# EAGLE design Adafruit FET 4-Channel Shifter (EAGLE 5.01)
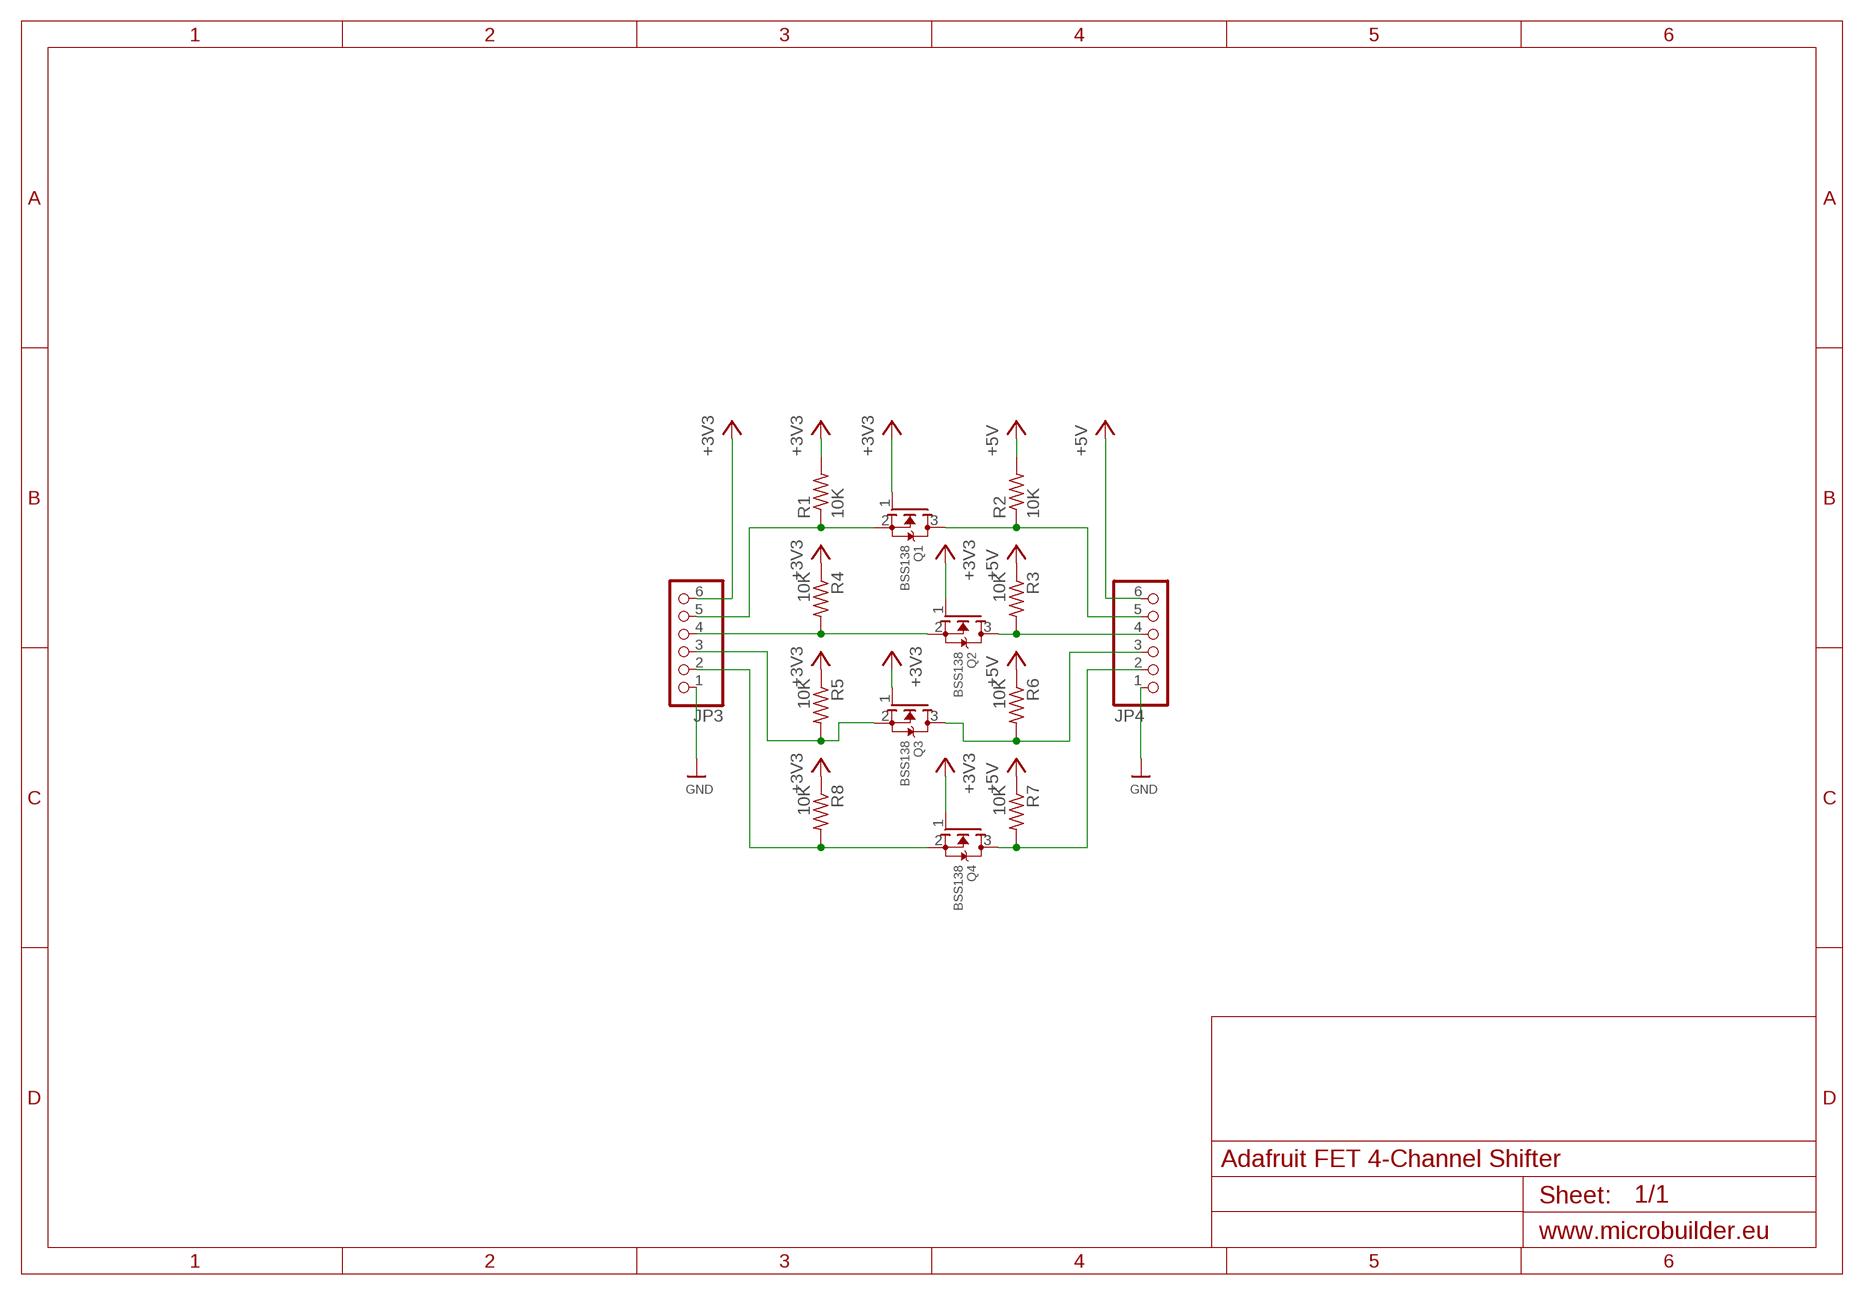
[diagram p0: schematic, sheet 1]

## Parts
JP3  PINHD-1X6CB  [1X06-CLEANBIG]
JP4  PINHD-1X6CB  [1X06-CLEANBIG]
Q1  BSS138  MOSFET-NREFLOW  [SOT23]
Q2  BSS138  MOSFET-NREFLOW  [SOT23]
Q3  BSS138  MOSFET-NREFLOW  [SOT23]
Q4  BSS138  MOSFET-NREFLOW  [SOT23]
R1  10K  R-US_R0805  [R0805]
R2  10K  R-US_R0805  [R0805]
R3  10K  R-US_R0805  [R0805]
R4  10K  R-US_R0805  [R0805]
R5  10K  R-US_R0805  [R0805]
R6  10K  R-US_R0805  [R0805]
R7  10K  R-US_R0805  [R0805]
R8  10K  R-US_R0805  [R0805]

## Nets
+3V3: JP3.6 Q1.1(G) Q2.1(G) Q3.1(G) Q4.1(G) R1.2 R4.1 R5.1 R8.1
+5V: JP4.6 R2.2 R3.1 R6.1 R7.1
GND: JP3.1 JP4.1
N$1: JP4.3 Q3.3(D) R6.2
N$2: JP4.5 Q1.3(D) R2.1
N$3: JP3.3 Q3.2(S) R5.2
N$4: JP3.2 Q4.2(S) R8.2
N$5: JP4.2 Q4.3(D) R7.2
N$6: JP3.4 Q2.2(S) R4.2
N$8: JP4.4 Q2.3(D) R3.2
N$9: JP3.5 Q1.2(S) R1.1

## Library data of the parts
JP3 JP4 = adafruit:PINHD-1X6: PIN HEADER
Q1-Q4 = adafruit:MOSFET-N: N-Channel Mosfet 2N7002E - 60V 260mA SOT23 [Digikey: 2N7002ET1GOSTR-ND] - REEL BSH103 - 30V 850mA SOT23 [Digikey: 568-5013-1-ND]
R1-R8 = adafruit:R-US_: RESISTOR, American symbol

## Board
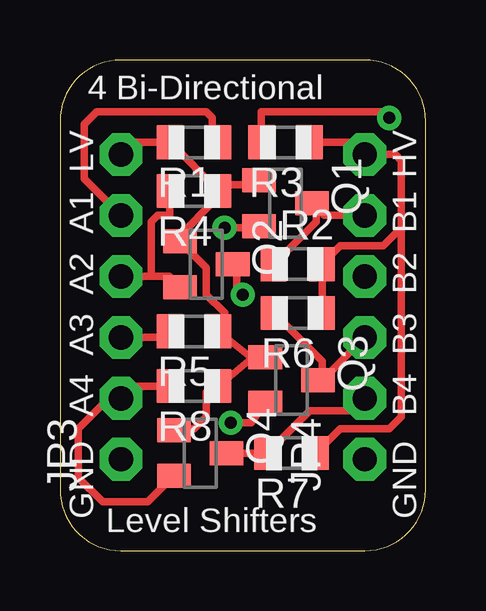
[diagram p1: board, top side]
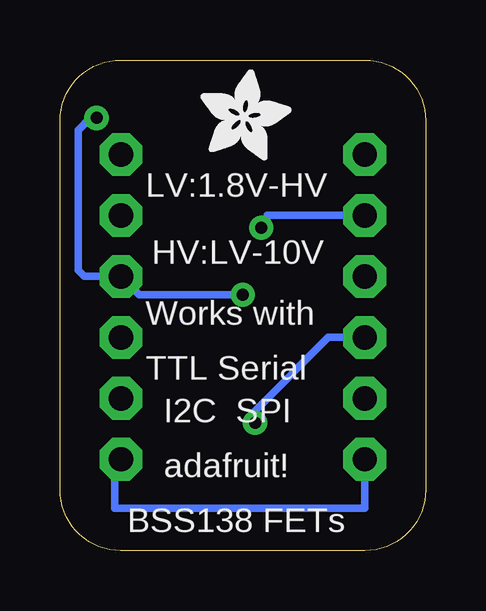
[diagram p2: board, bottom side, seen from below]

Size 15.24 x 20.45 mm. Coordinates in mm from the lower left corner, seen from the top.
Outline: 12.7,0 arc90 15.24,2.54 15.24,17.91 arc90 12.7,20.45 2.54,20.45 arc90 0,17.91 0,2.54 arc90 2.54,0 12.7,0
Copper layers (1*16): Top 0.035mm / dielectric 1.5mm / Bottom 0.035mm
Design rules "default *": minimum track width 8mil, minimum drill 0.4mm, track to track 8mil, track to pad 8mil, pad to pad 8mil, via to via 8mil, smd to smd 8mil, copper to edge 20mil, drill to drill 8mil, minimum pad ring 8mil, minimum via ring 10mil, stop-mask expansion 3mil, vias tented up to drill 20mil, thermal gap 8mil

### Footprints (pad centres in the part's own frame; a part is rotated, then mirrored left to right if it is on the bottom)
1X06-CLEANBIG = drill 1.016 pad 1.778 octagon: 1 -6.35,0; 2 -3.81,0; 3 -1.27,0; 4 1.27,0; 5 3.81,0; 6 6.35,0
SOT23 = smd 1 x 1.4: 1 -0.95,-1.1; 2 0.95,-1.1; 3 0,1.1
R0805 = smd 1.1 x 1.4: 1 -1,0; 2 1,0

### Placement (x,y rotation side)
JP3  2.54,10.16 90 top
JP4  12.7,10.16 90 top
Q1  9.4,14.48 270 top
Q2  6.1,11.94 270 top
Q3  9.65,7.11 270 top
Q4  5.84,4.06 270 top
R1  5.59,17.02 180 top
R2  9.91,11.94 0 top
R3  9.4,17.02 180 top
R4  5.59,14.99 180 top
R5  5.59,9.14 180 top
R6  9.91,9.91 180 top
R7  9.65,4.06 180 top
R8  5.59,6.86 180 top
U$1  [ADAFRUIT_3.5MM]  9.4,16.26 0 bottom

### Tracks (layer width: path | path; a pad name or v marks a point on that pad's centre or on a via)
+3V3
  Top 0.305: JP3.6 3.05,17.02 R1.2 6.62,14.99 | R4.1 6.62,14.99 | 6.62,14.99 6.86,14.99 | Q1.1 8.13,15.26 8.13,15.24 6.84,15.24 R4.1 | R4.1 6.35,14.99 6.35,14.5 5.08,13.21 5.08,12.97 Q2.1 6.1,11.79 6.1,10.67 6.86,9.91 6.86,9.16 R5.1 7.86,8.13 8.11,8.13 | 8.87,8.13 8.89,8.13 | 8.87,8.13 Q3.1 8.74,8.13 | 8.11,8.13 R8.1 6.86,6.86 6.86,6.35 6.35,6.86 6.1,6.6 6.1,5.59 5.59,5.08 4.81,5.08 Q4.1 | 8.74,8.13 8.87,8.13 | 8.11,8.13 8.38,8.13 8.74,8.13
+5V
  Top 0.305: R3.1 12.19,17.02 JP4.6 13.97,16.51 14.22,16.26 14.22,13.46 | R6.1 10.92,9.92 10.92,11.94 R2.2 11.67,12.7 13.46,12.7 14.22,13.46 | R7.1 11.67,5.08 13.72,5.08 14.22,5.59 14.22,13.46
GND
  Bottom 0.305: JP3.1 2.54,1.78 12.95,1.78 12.95,3.81 JP4.1
N$1
  Top 0.305: R6.2 10.92,7.89 10.92,7.11 | 10.92,7.11 Q3.3 | 10.92,7.11 JP4.3
N$2
  Top 0.305: Q1.3 11.01,13.97 JP4.5 | Q1.3 10.16,14.48 | Q1.3 10.67,14.48 10.67,13.7 R2.1
N$3  (via drill 0.5)
  Top 0.305: R5.2 4.59,8.89 JP3.3 | Q3.2 7.98,5.33 v7.11,5.33
  Bottom 0.305: v7.11,5.33 7.11,5.84 4.06,8.89 JP3.3
N$4
  Top 0.305: R8.2 3.05,6.86 JP3.2 2.03,6.35 0.76,5.08 0.76,3.05 1.78,2.03 3.66,2.03 Q4.2
N$5
  Top 0.305: JP4.2 12.19,5.84 10.41,5.84 8.64,4.06 R7.2 Q4.3 6.86,4.06
N$6
  Top 0.305: 2.29,11.43 JP3.4 3.81,11.43 | Q2.2 4.55,11.43 3.81,11.43 | 4.33,15.24 R4.2 4.57,14.97 4.57,13.97 4.06,13.97 3.81,13.72 3.81,11.43
N$8  (via drill 0.5)
  Top 0.305: Q2.3 7.37,11.94 7.37,10.92 v7.62,10.67 | R3.2 8.38,17.03 8.38,18.29 13.46,18.29 v13.72,18.03
  Bottom 0.305: v7.62,10.67 11.94,10.67 JP4.4 14.22,11.43 14.48,11.68 14.48,17.53 13.97,18.03 v13.72,18.03
N$9  (via drill 0.5)
  Top 0.305: JP3.5 1.02,15.49 1.02,17.78 1.52,18.29 6.1,18.29 6.35,18.03 6.35,17.02 R1.1 | Q1.2 8.23,13.46 v6.86,13.46
  Bottom 0.305: v6.86,13.46 6.6,13.97 JP3.5

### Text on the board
tPlace: 4 Bi-Directional | HV | LV | B1 | A1 | B2 | A2 | B3 | A3 | B4 | A4 | GND | GND | Level Shifters
bPlace: LV:1.8V-HV | HV:LV-10V | Works with | TTL Serial | I2C SPI | adafruit! | BSS138 FETs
